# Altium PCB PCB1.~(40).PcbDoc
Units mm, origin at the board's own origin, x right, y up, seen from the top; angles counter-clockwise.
Board outline 145.29 x 144.91 mm, 2 copper layers (Top Layer, Bottom Layer); 41 components, 36 nets, 219 pads, 0 vias.
Unrouted connection lines stored in the file: 9.
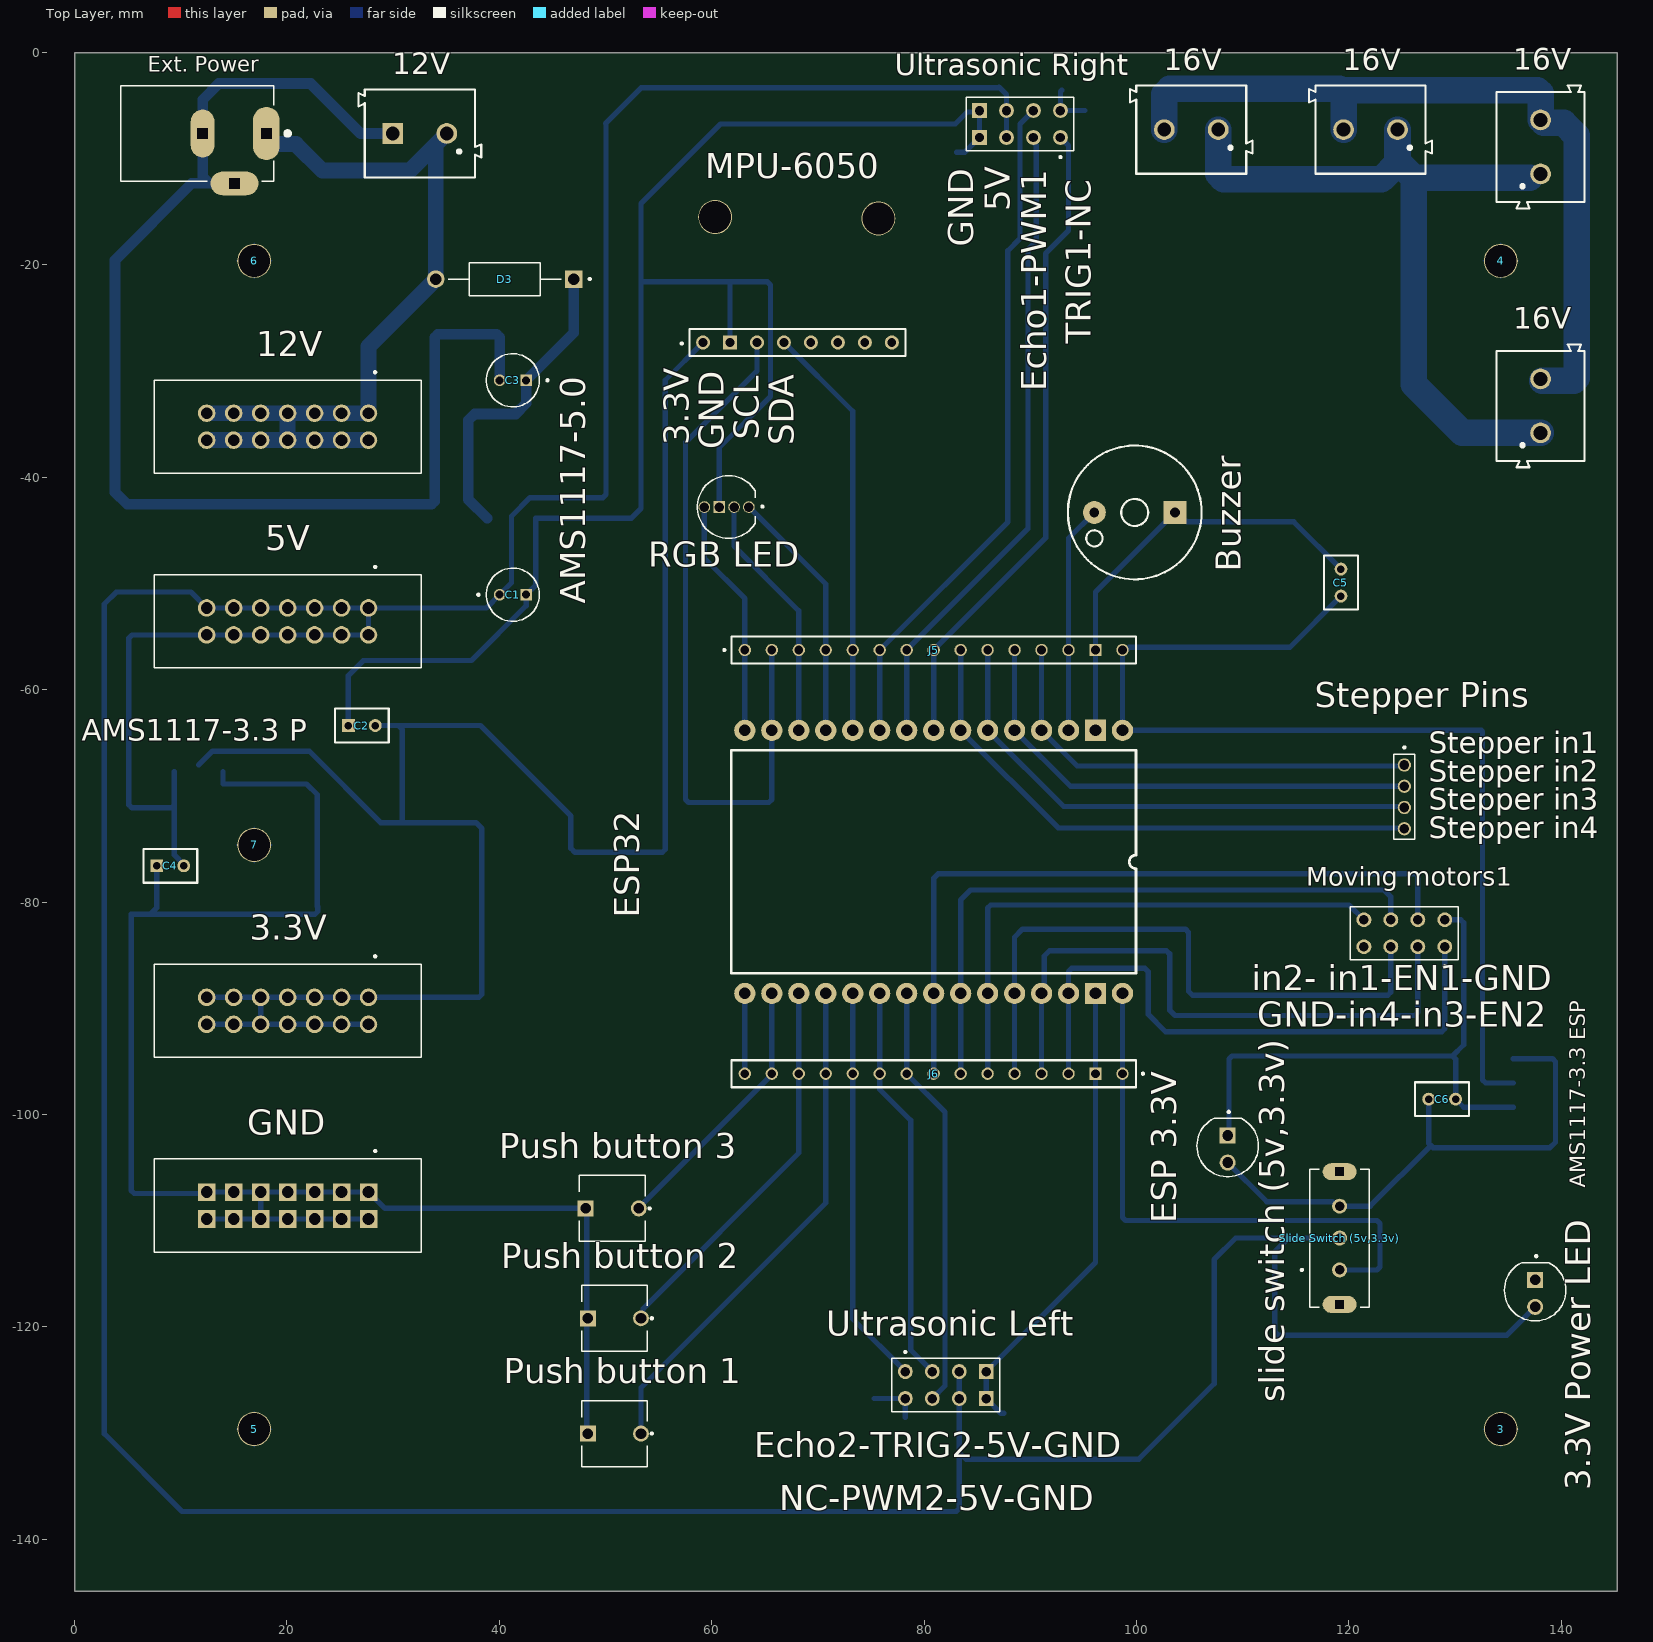
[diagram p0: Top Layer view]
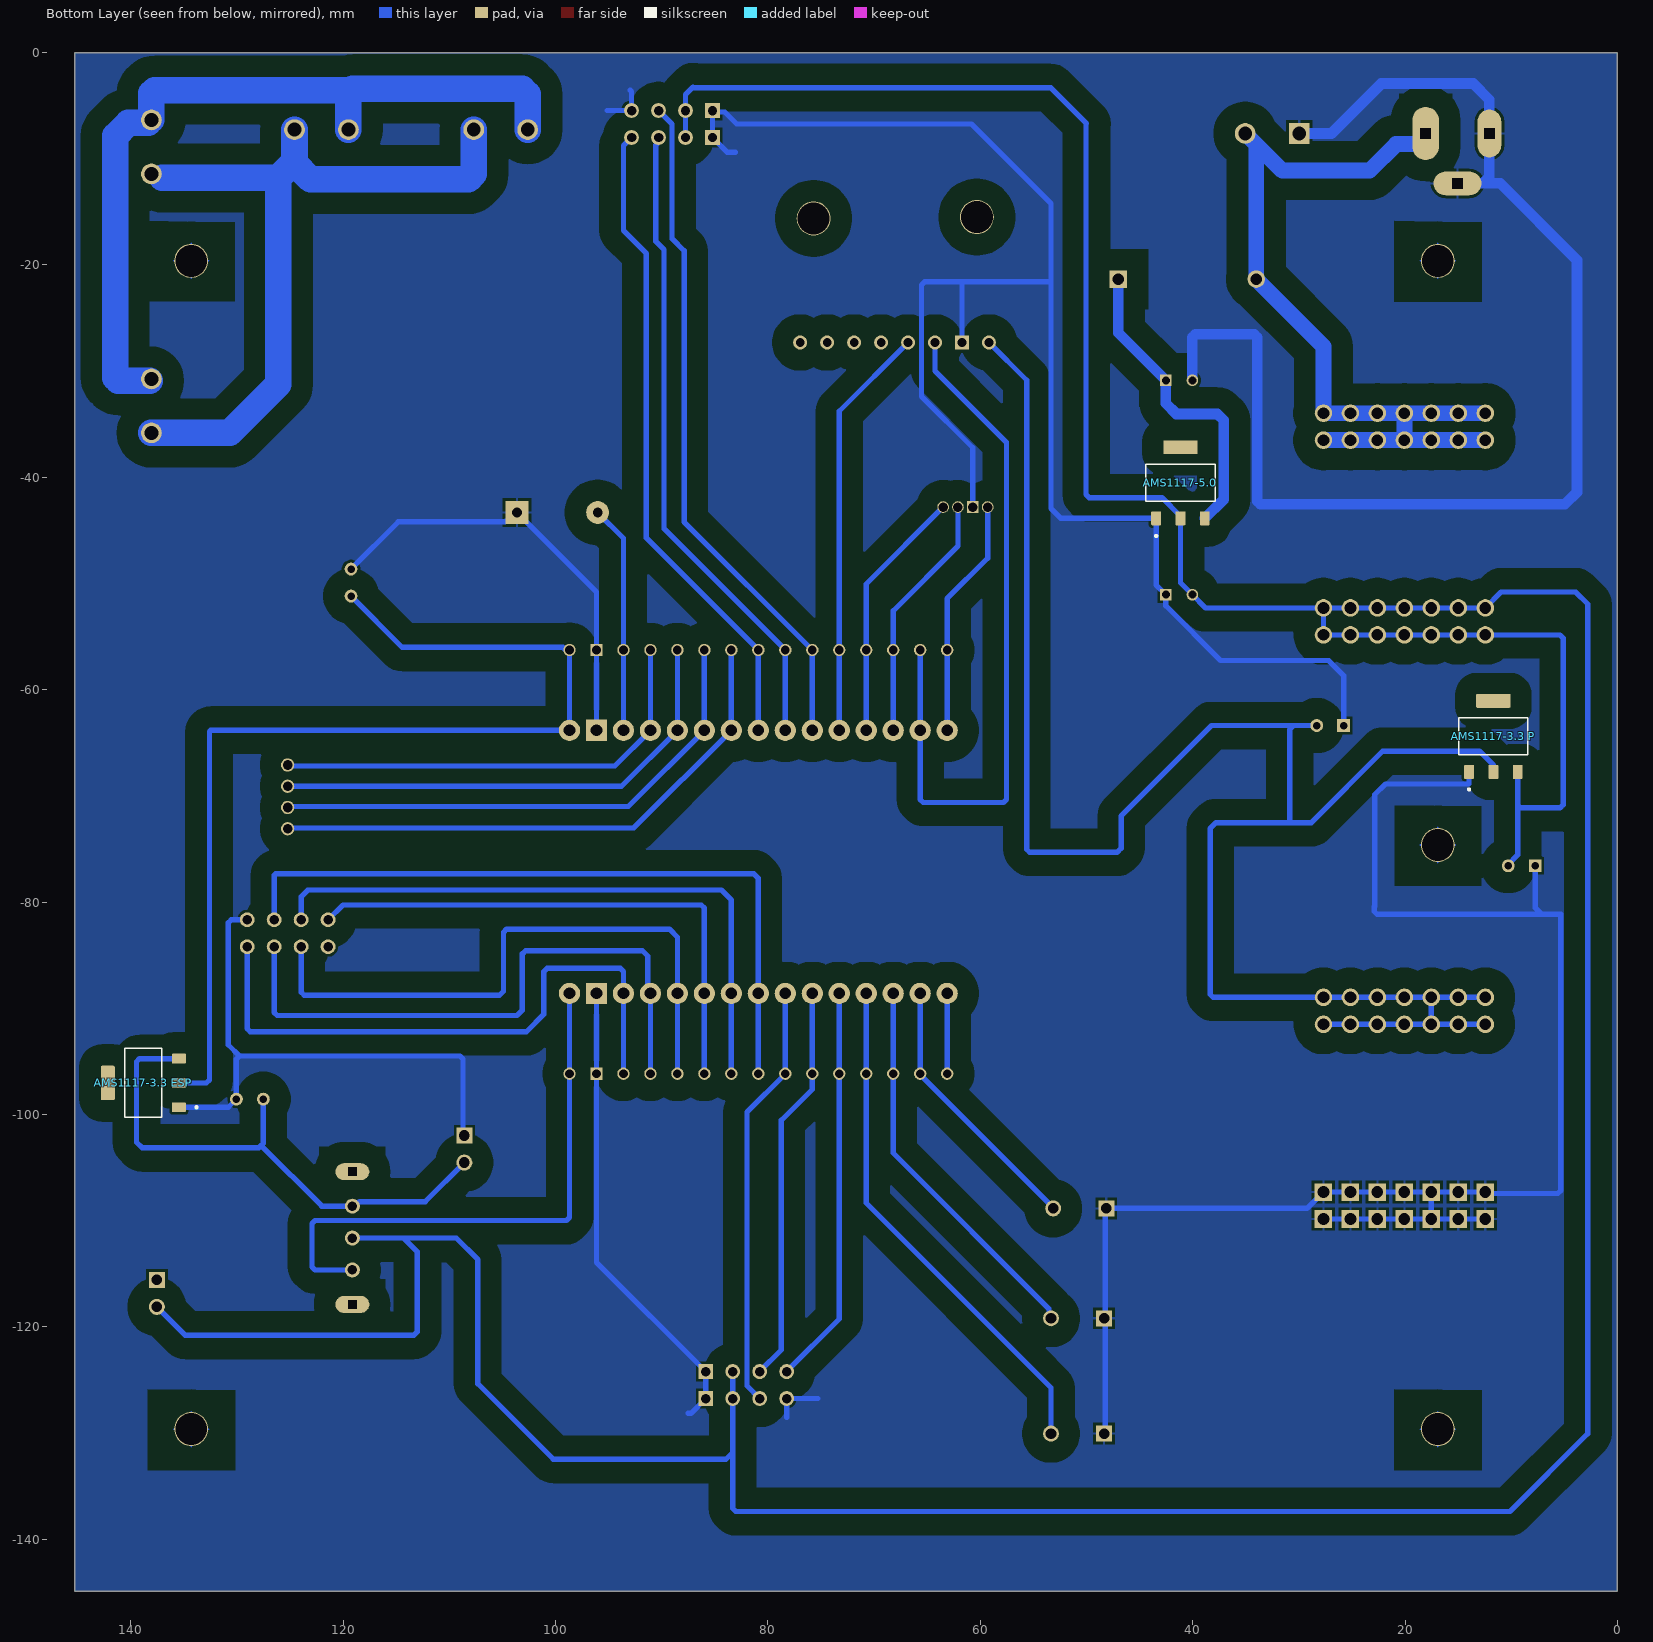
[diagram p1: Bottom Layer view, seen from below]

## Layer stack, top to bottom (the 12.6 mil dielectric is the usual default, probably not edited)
Top Solder: solder mask 0.0102, Solder Resist, Dk 3.5
Top Layer: signal copper 0.0356
Dielectric 1: dielectric 0.32, FR-4, Dk 4.8
Bottom Layer: signal copper 0.0356
Bottom Solder: solder mask 0.0102, Solder Resist, Dk 3.5

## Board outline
0,-144.907 145.288,-144.907 145.288,0 0,0

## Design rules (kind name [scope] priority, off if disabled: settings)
Clearance [All] p1: gap=0.254 ignorepadtopadclearanceinfootprint=FALSE except(0: Arc-Hole Track-Hole SMDPad-Hole THPad-Hole Via-Hole Fill-Hole Poly-Hole Region-Hole Text-Hole; 2: Arc-Poly Track-Poly SMDPad-Poly THPad-Poly)
PolygonConnect [All] p1: connectstyle=Relief reliefconductorwidth=0.254 reliefentries=4 polygonreliefangle="90 Angle" airgapwidth=0.254
RoutingLayers [All] p1: top layer_v5=FALSE bottom layer_v5=TRUE
RoutingVias [All] p1: holewidth=0.711 width=1.27 viastyle="Through Hole" minholewidth=0.711 minwidth=1.27 maxholewidth=0.711 maxwidth=1.27
SolderMaskExpansion [All] p1: expansion=0.102 istentingtop=FALSE
Width [All] p1: maxlimit=2.5 minlimit=0.254 preferedwidth=0.5
29 further rules are at their usual default settings.

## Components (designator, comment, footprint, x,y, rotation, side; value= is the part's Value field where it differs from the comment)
3 "Mounting Hole" PCBComponent_1 134.304,-129.619 r90 top
3.3V "3.3v pin headers block" AMPHENOL_52601-S14-4LF#1 20.066,-90.235 r180 top
"3.3V Power LED" "LED 5mm" "LED 5mm" 137.541,-116.84 r270 top
4 "Mounting Hole" PCBComponent_1 134.304,-19.619 r90 top
5 "Mounting Hole" PCBComponent_1 16.916,-129.619 r90 top
5V "5v pin headers block" AMPHENOL_52601-S14-4LF#1 20.066,-53.568 r180 top
6 "Mounting Hole" PCBComponent_1 16.916,-19.619 r90 top
7 "Mounting Hole" PCBComponent_1 16.916,-74.619 r90 top
12V "12v pin headers block" AMPHENOL_52601-S14-4LF#1 20.066,-35.235 r180 top
12V "From Buck" 691213510002#1 32.512,-7.62 r180 top
16V "From Buck" 691213510002#2 138.049,-8.89 r90 top
16V "From Buck" 691213510002#2 138.049,-33.274 r90 top
16V "From Buck" 691213510002#2 122.036,-7.26 r180 top
16V "From Buck" 691213510002#2 105.156,-7.26 r180 top
"AMS1117-3.3 ESP" "AMS1117-3.3" SOT229P700X180-4N 138.811,-97.028 r0 bottom
"AMS1117-3.3 P" "AMS1117-3.3" SOT229P700X180-4N 11.684,-64.389 r90 bottom
AMS1117-5.0 "AMS1117-5.0" SOT229P700X180-4N 41.148,-40.513 r90 bottom
Buzzer "Buzzer" "Buzzer 5V" 99.832,-43.307 r180 top
C1 "CAP  33UF 50V RADIAL" "CAP  33UF 50V RADIAL"#1 41.275,-51.054 r0 top
C2 "Ceramic Capacitor 100nF" C320C#1 34.051,-56.373 r0 top
C3 "CAP  33UF 50V RADIAL" "CAP  33UF 50V RADIAL"#2 41.275,-30.861 r180 top
C4 "Ceramic Capacitor 100nF" C320C#1 16.017,-69.581 r0 top
C5 "Ceramic Capacitor 100nF" C320C#2 126.253,-56.911 r270 top
C6 "Ceramic Capacitor 100nF" C320C#2 121.778,-105.552 r180 top
D3 "RL207" DIOAD1300W80L670D310 40.513,-21.336 r180 top
ESP32 "ESP32DEVKITV1" ESP32DEVKITV1 81.026,-75.508 r90 top
"ESP 3.3V" "LED 5mm" "LED 5mm" 108.585,-103.251 r270 top (schematic designator "Power ESP 3.3V")
"Ext. Power" "DC Power Jack Female Socket" "DC Power Jack Female Socket" 18.065,-7.62 r180 top
GND "GND pin headers block" AMPHENOL_52601-S14-4LF#2 20.066,-108.568 r180 top
J5 "TS-115-T-A-1" SAMTEC_TS-115-T-A-1#1 80.899,-56.261 r0 top
J6 "TS-115-T-A-1" SAMTEC_TS-115-T-A-1#2 80.899,-96.157 r180 top
"Moving motors1" "Pin header female block 8 pin" "Pin header female block 8 pin"#1 125.222,-82.931 r180 top
MPU-6050 "MPU-6050" MPU-6050 57.658,-28.829 r90 top
"Push button 1" "FSM8JRT" TE_FSM8JRT 53.34,-130.048 r180 top
"Push button 2" "FSM8JRT" TE_FSM8JRT 53.34,-119.189 r180 top
"Push button 3" "FSM8JRT" TE_FSM8JRT 53.137,-108.839 r180 top
"RGB LED" "common cathode" "LED RGB 5mm" 61.595,-42.799 r180 top
"Slide Switch (5v,3.3v)" "slide switch (5v,3.3v)" "Slide switch" 119.126,-111.633 r90 top
"Stepper Pins" "Pin hreader 4 pins" "Pin hreader 4 pins" 125.222,-67.088 r270 top
"Ultrasonic Left" "Pin header female block 8 pin" "Pin header female block 8 pin"#2 82.042,-125.476 r0 top
"Ultrasonic Right" "Pin header female block 8 pin" "Pin header female block 8 pin"#2 89.027,-6.731 r180 top

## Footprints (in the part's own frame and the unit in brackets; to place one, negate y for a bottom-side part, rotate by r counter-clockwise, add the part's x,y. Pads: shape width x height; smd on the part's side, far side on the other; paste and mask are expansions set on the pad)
691213510002#1 [mm]
  round 1.95 hole 1.3: 1(-2.54,0)
  rect 1.95x1.95 hole 1.3: 2(2.54,0)
  silkscreen extent -5.78,-4.15 5.78,4.15, body extent -5.68,-3.94 5.68,4.16, height 10
691213510002#2 [mm]
  round 1.95 hole 1.3: 1(-2.54,0) 2(2.54,0)
  silkscreen extent -5.78,-4.15 5.78,4.15, body extent -5.68,-3.94 5.68,4.16, height 10
AMPHENOL_52601-S14-4LF#1 [mm]
  round 1.65 hole 1.1: 1(-7.62,-1.27) 2(-7.62,1.27) 3(-5.08,-1.27) 4(-5.08,1.27) 5(-2.54,-1.27) 6(-2.54,1.27) 7(0,-1.27) 8(0,1.27) 9(2.54,-1.27) 10(2.54,1.27) 11(5.08,-1.27) 12(5.08,1.27) 13(7.62,-1.27) 14(7.62,1.27)
  silkscreen extent -12.57,-5.23 12.57,4.38, body extent -12.57,-4.38 12.57,4.38, height 9.53
AMPHENOL_52601-S14-4LF#2 [mm]
  rect 1.65x1.65 hole 1.1: 1(-7.62,-1.27) 2(-7.62,1.27) 3(-5.08,-1.27) 4(-5.08,1.27) 5(-2.54,-1.27) 6(-2.54,1.27) 7(0,-1.27) 8(0,1.27) 9(2.54,-1.27) 10(2.54,1.27) 11(5.08,-1.27) 12(5.08,1.27) 13(7.62,-1.27) 14(7.62,1.27)
  silkscreen extent -12.57,-5.23 12.57,4.38, body extent -12.57,-4.38 12.57,4.38, height 9.53
"Buzzer 5V" [mil]
  rect 85x85 hole 36: NEG(-149.61,0)
  round 85 hole 36: POS(149.61,0)
  silkscreen extent -248,-248 248,248, body extent -236,-236 236,236, height 394
C320C#1 [mm]
  rect 1.21x1.21 hole 0.71: 1(-8.27,-7)
  round 1.21 hole 0.71: 2(-5.73,-7)
  silkscreen extent -9.54,-8.59 -4.46,-5.41, body extent -9.53,-8.57 -4.45,-5.4, height 7.1
C320C#2 [mm]
  round 1.21 hole 0.71: 1(-8.27,-7) 2(-5.73,-7)
  silkscreen extent -9.54,-8.59 -4.46,-5.41, body extent -9.52,-8.57 -4.45,-5.4, height 7.1
"CAP  33UF 50V RADIAL"#1 [mm]
  rect 1.1x1.1 hole 0.75: N(1.25,0)
  round 1.1 hole 0.75: P(-1.25,0)
  silkscreen extent -3.35,-2.5 2.5,2.5, body extent -2.49,-2.5 2.5,2.5, height 11
"CAP  33UF 50V RADIAL"#2 [mm]
  round 1.1 hole 0.75: N(1.25,0)
  rect 1.1x1.1 hole 0.75: P(-1.25,0)
  silkscreen extent -3.35,-2.5 2.5,2.5, body extent -2.49,-2.5 2.5,2.5, height 11
"DC Power Jack Female Socket" [mm]
  oval 2.5x5 hole 1 square: 1(0,0)
  oval 2.25x4.5 hole 1 square: 2(6,0)
  oval 4.5x2.25 hole 1 square: 3(3,4.7)
  silkscreen extent -2.2,-4.5 13.7,4.5, body extent -0.7,-4.5 13.7,4.9, height 11
DIOAD1300W80L670D310 [mm]
  round 1.65 hole 1.1: A(6.5,0)
  rect 1.65x1.65 hole 1.1: C(-6.5,0)
  silkscreen extent -8.1,-1.55 5.32,1.55, body extent -6.9,-1.95 6.9,1.65, height 3.6
ESP32DEVKITV1 [mm]
  round 2 hole 1.1: 1(11.684,-17.653) 3(11.684,-12.573) 4(11.684,-10.033) 5(11.684,-7.493) 6(11.684,-4.953) 7(11.684,-2.413) 8(11.684,0.127) 9(11.684,2.667) 10(11.684,5.207) 11(11.684,7.747) 12(11.684,10.287) 13(11.684,12.827) 14(11.684,15.367) 15(11.684,17.907) 16(-13.086,17.907) 17(-13.086,15.367) 18(-13.086,12.827) 19(-13.086,10.287) 20(-13.086,7.747) 21(-13.086,5.207) 22(-13.086,2.667) 23(-13.086,0.127) 24(-13.086,-2.413) 25(-13.086,-4.953) 26(-13.086,-7.493) 27(-13.086,-10.033) 28(-13.086,-12.573) 30(-13.086,-17.653)
  rect 2x2 hole 1.1: 2(11.684,-15.113) 29(-13.086,-15.113)
  silkscreen extent -11.2,-18.92 9.79,19.18, body extent -15.13,-28.49 13.86,24.48, height 8.36
"LED 5mm" [mm]
  round 1.508 hole 1: A(1.27,0)
  rect 1.508x1.508 hole 1: C(-1.27,0)
  silkscreen extent -3.6,-2.9 2.6,2.9, body extent -2.88,-2.9 2.51,2.9, height 12.1
"LED RGB 5mm" [mm]
  round 1.1 hole 0.9: 1(-1.905,0) 2(-0.508,0) 4(2.286,0)
  rect 1.1x1.1 hole 0.9: 3(0.889,0)
  silkscreen extent -3.27,-2.95 2.95,2.95, body extent -2.47,-3.05 2.98,2.84, height 9.6
MPU-6050 [mil]
  round 52 hole 32: 01(60,-60) 03(60,-260) 04(60,-360) 05(60,-460) 06(60,-560) 07(60,-660) 08(60,-760)
  rect 52x52 hole 32: 02(60,-160)
  round 125.98 hole 118.11: ""(520,-710) ""(525,-105)
  silkscreen extent 10,-810 110,23, body extent 15,-811 615,-9, height 612
PCBComponent_1 [mm]
  round 3.2 hole 3: ""(0,0)
  Bottom Layer lines w0.15: 0,1.649 0,-1.651 ; -1.651,0 1.649,0
"Pin header female block 8 pin"#1 [mm]
  round 1.398 hole 0.89: 1(-3.81,1.27) 2(-1.27,1.27) 3(1.27,1.27) 4(3.81,1.27) 5(-3.81,-1.27) 6(-1.27,-1.27) 7(1.27,-1.27) 8(3.81,-1.27)
  silkscreen extent -5.08,-2.52 5.08,3.21, body extent -5.08,-2.51 5.08,2.51, height 6.22
"Pin header female block 8 pin"#2 [mm]
  round 1.398 hole 0.89: 1(-3.81,1.27) 2(-1.27,1.27) 3(1.27,1.27) 5(-3.81,-1.27) 6(-1.27,-1.27) 7(1.27,-1.27)
  rect 1.398x1.398 hole 0.89: 4(3.81,1.27) 8(3.81,-1.27)
  silkscreen extent -5.08,-2.52 5.08,3.21, body extent -5.08,-2.51 5.08,2.51, height 6.22
"Pin hreader 4 pins" [mm]
  round 1.25 hole 0.9: 1(0,0) 2(2,0) 3(4,0) 4(6,0)
  silkscreen extent -1.75,-1 7,1, body extent -1.01,-1.02 6.98,0.98, height 5.78
SAMTEC_TS-115-T-A-1#1 [mil]
  round 45.78 hole 32: 01(-700,0) 02(-600,0) 03(-500,0) 04(-400,0) 05(-300,0) 06(-200,0) 07(-100,0) 08(0,0) 09(100,0) 10(200,0) 11(300,0) 12(400,0) 13(500,0) 15(700,0)
  rect 45.78x45.78 hole 32: 14(600,0)
  silkscreen extent -780,-50 750,50, body extent -754,-50 754,50, height 326
SAMTEC_TS-115-T-A-1#2 [mil]
  round 45.78 hole 32: 01(-700,0) 03(-500,0) 04(-400,0) 05(-300,0) 06(-200,0) 07(-100,0) 08(0,0) 09(100,0) 10(200,0) 11(300,0) 12(400,0) 13(500,0) 14(600,0) 15(700,0)
  rect 45.78x45.78 hole 32: 02(-600,0)
  silkscreen extent -780,-50 750,50, body extent -754,-50 754,50, height 326
"Slide switch" [mm]
  round 1.408 hole 0.9: 1(-3,0) 2(0,0) 3(3,0)
  oval 1.6x3.2 hole 0.8 square: SH1(-6.25,0) SH2(6.25,0)
  silkscreen extent -6.5,-2.8 6.5,3.66, body extent -6.5,-5.8 6.5,2.8, height 6
SOT229P700X180-4N [mm]
  rrect15% 1.31x0.93 smd: 1(-3.345,2.29) 2(-3.345,0) 3(-3.345,-2.29)
  rrect15% 1.31x3.24 smd: 4(3.345,0)
  silkscreen extent -5.1,-3.25 1.75,3.25, body extent -3.5,-3.25 3.5,3.25, height 1.8
TE_FSM8JRT [mil]
  round 59 hole 39: 1(0,0)
  rect 59x59 hole 39: 2(197,0)
  silkscreen extent -44,-122 221,122, body extent -22,-122 222,122, height 372

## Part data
3.3V 5V 12V GND: library part 52601-S14-4LF, Package=None
"3.3V Power LED" "ESP 3.3V": "Red 623nm LED Indication - Discrete 1.9V Radial", Package=None
12V 16V 16V 16V 16V: library part "Terminal Block", "2 Position Wire to Board Terminal Block Horizontal with Board 0.200 (5.08mm) Through Hole", Package=None
"AMS1117-3.3 ESP" "AMS1117-3.3 P" AMS1117-5.0 J5 J6 "Moving motors1" "Stepper Pins" "Ultrasonic Left" "Ultrasonic Right": Package=None
Buzzer: library part "Buzzer 5V", "BUZZER 2.3KHZ 4-6VDC", Package=None
C1 C3: "NHG-A", Package=None
C2 C4 C5 C6: "0.1ÂµF Â±20% 50V Ceramic Capacitor Z5U Radial", Package="Radial KEMET"
D3: "Semiconductors and Actives, Power Diodes, Discretes (diodes, transistors, thyristors ...), Diodes", Package=None
"Ext. Power": "2.0 mm Center Pin, 2.5 A, Right Angle, Through Hole, Dc Power Jack Connector", Package=None
"Push button 1" "Push button 2" "Push button 3": "Tactile Switches PUSHBUTTON SWITCH TACT", Package=None
"RGB LED": library part "LED RGB 5mm", Package=None
"Slide Switch (5v,3.3v)": library part "Slide switch", Package=None

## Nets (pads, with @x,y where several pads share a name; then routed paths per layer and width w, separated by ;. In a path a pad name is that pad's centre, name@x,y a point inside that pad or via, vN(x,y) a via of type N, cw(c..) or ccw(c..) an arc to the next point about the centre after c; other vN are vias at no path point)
3.3V: 3.3V.1 3.3V.2 3.3V.3 3.3V.4 3.3V.5 3.3V.6 3.3V.7 3.3V.8 3.3V.9 3.3V.10 3.3V.11 3.3V.12 3.3V.13 3.3V.14 "AMS1117-3.3 P.2" C2.2 MPU-6050.01 | length 182.3
  Bottom Layer w0.5: 11.684,-67.095 12.993,-65.786 22.098,-65.786 28.829,-72.517 30.861,-72.517 ; 3.3V.14 3.3V.12 3.3V.10 ; 3.3V.13 3.3V.11 3.3V.9 ; 3.3V.2 3.3V.4 3.3V.6 3.3V.8 3.3V.10 ; C2.2 30.48,-63.373 ; MPU-6050.01 55.626,-30.861 55.626,-75.018 55.333,-75.311 47.117,-75.311 46.736,-74.93 46.736,-71.882 38.227,-63.373 30.48,-63.373 ; 3.3V.10 3.3V.9 ; 3.3V.9 3.3V.7 3.3V.5 3.3V.3 3.3V.1 38.061,-88.965 38.354,-88.672 38.354,-73.064 37.807,-72.517 30.861,-72.517 ; 30.48,-63.373 30.861,-63.754 30.861,-72.517
+5: 5V.1 5V.2 5V.3 5V.4 5V.5 5V.6 5V.7 5V.8 5V.9 5V.10 5V.11 5V.12 5V.13 5V.14 "3.3V Power LED.A" "AMS1117-3.3 P.3" "Slide Switch (5v,3.3v).2" "Ultrasonic Left.3" "Ultrasonic Left.7" "Ultrasonic Right.3" "Ultrasonic Right.7" AMS1117-5.0.2 C1.P C4.2 | length 450.9
  Bottom Layer w0.5: 9.394,-67.734 9.394,-70.827 ; C4.2 10.287,-76.451 9.394,-75.558 9.394,-70.827 ; 83.312,-124.206 83.312,-126.746 83.312,-131.826 ; 87.757,-8.001 87.757,-5.461 87.757,-3.954 87.05,-3.247 86.995,-3.302 53.373,-3.302 49.991,-6.684 50.038,-6.731 50.038,-41.617 49.745,-41.91 42.906,-41.91 41.148,-43.668 AMS1117-5.0.2 41.148,-49.931 C1.P 38.781,-52.298 5V.1 ; 119.126,-111.633 114.3,-111.633 ; 137.541,-118.11 134.874,-120.777 113.323,-120.777 113.03,-120.484 113.03,-112.903 114.3,-111.633 ; 9.394,-70.827 9.101,-71.12 5.412,-71.12 5.119,-70.827 5.119,-55.131 5.412,-54.838 5V.14 5V.12 5V.10 5V.8 5V.6 5V.4 5V.2 5V.1 ; 5V.1 5V.3 5V.5 5V.7 5V.9 5V.11 5V.13 10.948,-50.8 3.937,-50.8 2.794,-51.943 2.794,-130.048 10.125,-137.379 83.019,-137.379 83.312,-137.086 83.312,-131.826 ; 83.312,-131.826 83.947,-132.461 100.203,-132.461 107.315,-125.349 107.315,-113.665 109.347,-111.633 114.3,-111.633
+12: 12V.1 12V.2@27.686,-36.505 12V.3 12V.4 12V.5 12V.6 12V.7 12V.8 12V.9 12V.10 12V.11 12V.12 12V.13 12V.14 "Ext. Power.1" D3.A | length 82.3
  Bottom Layer w0.5: 18.065,-7.62 18.065,-7.696 18.989,-8.62 ; 34.013,-9.021 35.052,-7.981 12V.1@35.052,-7.62
  Bottom Layer w1.5: 12V.14 12V.12 12V.10 12V.8 ; 12V.13 12V.11 12V.9 12V.7 ; 18.989,-8.62 20.845,-8.62 23.345,-11.12 31.552,-11.12 12V.1@35.052,-7.62 ; 12V.2@27.686,-36.505 12V.4 12V.6 12V.8 ; D3.A 27.686,-27.663 27.686,-33.965 12V.3 12V.5 12V.7 ; D3.A@34.013,-21.313 34.013,-9.021 ; 12V.8 12V.7
GND: 12V.2@29.972,-7.62 "3.3V Power LED.C" "AMS1117-3.3 ESP.1" "AMS1117-3.3 P.1" "ESP 3.3V.C" "Ext. Power.2" "Ext. Power.3" "Moving motors1.4" "Moving motors1.5" "Push button 1.2" "Push button 2.2" "Push button 3.2" "RGB LED.3" "Ultrasonic Left.4" "Ultrasonic Left.5" "Ultrasonic Left.8" "Ultrasonic Right.4" "Ultrasonic Right.5" "Ultrasonic Right.8" AMS1117-5.0.1 Buzzer.NEG C1.N C2.1 C3.N C4.1 C5.1 C6.1 ESP32.2 ESP32.29 GND.1 GND.2 GND.3 GND.4 GND.5 GND.6 GND.7 GND.8 GND.9 GND.10 GND.11 GND.12 GND.13 GND.14 J5.14 J6.02 MPU-6050.02 | length 575.7
  Bottom Layer w0.5: C4.1 7.747,-80.518 7.112,-81.153 ; GND.14 GND.12 GND.10 ; 13.974,-67.734 13.974,-68.877 21.848,-68.877 22.86,-69.889 22.86,-80.391 22.915,-80.446 22.915,-80.86 22.622,-81.153 7.112,-81.153 ; C2.1 25.781,-58.674 27.201,-57.254 37.361,-57.254 42.525,-52.09 C1.N 43.438,-50.141 AMS1117-5.0.1 52.408,-43.858 53.34,-42.926 53.34,-21.463 ; GND.2 GND.4 GND.6 GND.8 GND.10 ; 33.616,-42.545 33.909,-42.252 ; 33.909,-26.836 34.202,-26.543 ; 39.732,-26.543 40.025,-26.836 ; 48.336,-130.048 48.235,-129.946 48.235,-108.941 48.133,-108.839 29.227,-108.839 GND.1 GND.3 GND.5 GND.7 GND.9 ; 60.706,-42.799 60.706,-37.211 65.532,-32.385 65.532,-21.883 65.239,-21.59 61.722,-21.59 ; MPU-6050.02 61.722,-21.59 ; 75.311,-126.746 78.232,-126.746 78.232,-128.524 ; 83.058,-9.398 83.82,-9.398 85.217,-8.001 85.217,-5.461 85.077,-5.601 84.061,-5.601 82.931,-6.731 60.833,-6.731 53.34,-14.224 53.34,-21.463 ; 87.503,-128.143 87.249,-128.143 85.852,-126.746 85.852,-124.206 96.139,-113.919 J6.02 ESP32.29 ; 92.964,-3.556 92.837,-3.683 92.837,-5.461 95.123,-5.461 ; ESP32.2 J5.14 96.139,-50.8 Buzzer.NEG 104.462,-44.137 104.695,-44.137 104.754,-44.196 114.808,-44.196 C5.1 ; 108.585,-101.981 108.712,-101.854 108.712,-94.781 109.005,-94.488 129.755,-94.488 ; 129.032,-81.661 130.517,-81.661 130.81,-81.954 130.81,-93.433 129.755,-94.488 ; 135.466,-99.318 130.814,-99.318 C6.1 130.048,-94.781 129.755,-94.488 ; 7.112,-81.153 5.334,-81.153 5.334,-107.149 5.627,-107.442 12.302,-107.442 GND.13 GND.11 GND.9 ; GND.10 GND.9 ; 53.34,-21.463 53.467,-21.59 61.722,-21.59
  Bottom Layer w1: 15.065,-12.32 12.701,-12.32 ; 12V.2@29.972,-7.62 26.924,-7.62 22.225,-2.921 13.589,-2.921 12.065,-4.445 12.065,-11.684 12.701,-12.32 ; 33.616,-42.545 4.953,-42.545 3.81,-41.402 3.81,-19.558 11.048,-12.32 12.701,-12.32 ; 33.909,-42.252 33.909,-26.836 ; 34.202,-26.543 39.732,-26.543 ; C3.N 40.025,-26.836
Net16V_1: 16V.1 | length 72.4
  Bottom Layer w0.5: 137.031,-11.811 137.135,-11.707 137.772,-11.707 16V.1@138.049,-11.43
  Bottom Layer w2.5: 16V.1@107.696,-7.26 107.696,-11.43 108.204,-11.938 123.053,-11.938 124.576,-10.415 ; 16V.1@124.576,-7.26 124.576,-10.276 126.111,-11.811 ; 137.031,-11.811 126.111,-11.811 ; 16V.1@138.049,-35.814 130.683,-35.814 126.111,-31.242 126.111,-11.811
Net16V_2: 16V.2 | length 75.7
  Bottom Layer w0.5: 102.616,-3.937 103.124,-3.429 ; 119.077,-3.429 119.496,-3.849 119.789,-3.556 ; 137.756,-3.556 138.049,-3.849 ; 16V.2@138.049,-30.734 16V.2@138.21,-30.895 ; 16V.2@138.049,-6.35 16V.2@138.326,-6.627 ; 141.151,-30.895 141.444,-30.602
  Bottom Layer w2.5: 16V.2@102.616,-7.26 102.616,-3.937 ; 103.124,-3.429 119.077,-3.429 ; 16V.2@119.496,-7.26 119.496,-3.849 ; 119.789,-3.556 137.756,-3.556 ; 16V.2@138.049,-6.35 138.049,-3.849 ; 16V.2@138.21,-30.895 141.151,-30.895 ; 16V.2@138.326,-6.627 140.231,-6.627 141.444,-7.84 141.444,-30.602
"NetAMS1117-3.3 ESP_2": "AMS1117-3.3 ESP.2" C5.2 ESP32.1 J5.15 | length 100
  Bottom Layer w0.5: C5.2 114.427,-56.007 99.303,-56.007 99.176,-56.134 98.806,-56.134 J5.15 ESP32.1 132.461,-63.824 132.588,-63.951 132.588,-96.735 132.881,-97.028 135.466,-97.028
"NetAMS1117-3.3 ESP_3": "AMS1117-3.3 ESP.3" "ESP 3.3V.A" "Slide Switch (5v,3.3v).3" C6.2 | length 51.4
  Bottom Layer w0.5: 108.585,-104.521 112.268,-108.204 118.451,-108.204 118.88,-108.633 119.126,-108.633 121.999,-108.633 127.718,-102.914 ; C6.2 127.508,-102.704 127.718,-102.914 ; 135.466,-94.738 139.153,-94.738 139.446,-95.031 139.446,-102.616 138.938,-103.124 127.928,-103.124 127.718,-102.914
NetAMS1117-5.0_3: AMS1117-5.0.3 C3.P D3.C | length 29.6
  Bottom Layer w1: AMS1117-5.0.3 37.084,-42.084 37.084,-34.622 37.67,-34.036 41.529,-34.036 42.525,-33.04 C3.P 47.013,-26.373 D3.C
NetBuzzer_POS: Buzzer.POS ESP32.3 J5.13 | length 21.5
  Bottom Layer w0.5: ESP32.3 J5.13 93.599,-45.74 Buzzer.POS
NetESP32_4: "Stepper Pins.1" ESP32.4 J5.12 | length 42.6
  Bottom Layer w0.5: J5.12 ESP32.4 94.418,-67.183 124.714,-67.183
NetESP32_5: "Stepper Pins.2" ESP32.5 J5.11 | length 46.1
  Bottom Layer w0.5: J5.11 ESP32.5 93.783,-69.088 124.841,-69.088
NetESP32_6: "Stepper Pins.3" ESP32.6 J5.10 | length 49.3
  Bottom Layer w0.5: J5.10 ESP32.6 93.148,-70.993 124.714,-70.993
NetESP32_7: "Stepper Pins.4" ESP32.7 J5.09 | length 52.5
  Bottom Layer w0.5: J5.09 ESP32.7 92.64,-73.025 124.587,-73.025
NetESP32_8: "Ultrasonic Right.1" ESP32.8 J5.08 | length 61.4
  Bottom Layer w0.5: ESP32.8 J5.08 91.44,-45.72 91.44,-18.923 93.599,-16.764 93.599,-8.763 92.837,-8.001
NetESP32_9: "Ultrasonic Right.2" ESP32.9 J5.07 | length 61
  Bottom Layer w0.5: ESP32.9 J5.07 89.789,-44.831 89.789,-18.542 90.551,-17.78 90.551,-8.743 90.469,-8.661 90.469,-8.173 90.297,-8.001
NetESP32_10: "Ultrasonic Right.6" ESP32.10 J5.06 | length 64.4
  Bottom Layer w0.5: ESP32.10 J5.06 87.884,-44.196 87.884,-18.669 89.027,-17.526 89.027,-6.731 90.297,-5.461
NetESP32_11: ESP32.11 J5.05 MPU-6050.04 | length 39.2
  Bottom Layer w0.5: MPU-6050.04 73.279,-33.782 ESP32.11
NetESP32_12: "RGB LED.1" ESP32.12 J5.04 | length 24
  Bottom Layer w0.5: 63.5,-42.799 70.739,-50.038 J5.04 ESP32.12
NetESP32_13: "RGB LED.2" ESP32.13 J5.03 | length 23.6
  Bottom Layer w0.5: 62.103,-42.799 62.103,-46.474 68.199,-52.57 J5.03 ESP32.13
NetESP32_14: ESP32.14 J5.02 MPU-6050.03 | length 68.2
  Bottom Layer w0.5: MPU-6050.03 64.262,-29.972 57.531,-36.703 57.531,-70.319 57.824,-70.612 65.366,-70.612 65.659,-70.319 ESP32.14 J5.02
NetESP32_15: "RGB LED.4" ESP32.15 J5.01 | length 22.6
  Bottom Layer w0.5: 59.309,-42.799 59.309,-47.617 63.119,-51.427 J5.01 ESP32.15
NetESP32_16: ESP32.16 J6.15 | length 7.6
  Bottom Layer w0.5: J6.15 ESP32.16
NetESP32_17: "Push button 3.1" ESP32.17 J6.14 | length 25.4
  Bottom Layer w0.5: 53.137,-108.839 53.137,-108.759 65.659,-96.237 J6.14 ESP32.17
NetESP32_18: "Push button 2.1" ESP32.18 J6.13 | length 36.8
  Bottom Layer w0.5: 53.34,-119.189 53.531,-118.998 53.531,-118.3 68.199,-103.632 J6.13 ESP32.18
NetESP32_19: "Push button 1.1" ESP32.19 J6.12 | length 48.7
  Bottom Layer w0.5: 53.34,-130.048 53.34,-125.73 70.739,-108.331 J6.12 ESP32.19
NetESP32_20: "Ultrasonic Left.1" ESP32.20 J6.11 | length 37.7
  Bottom Layer w0.5: ESP32.20 73.279,-119.253 78.232,-124.206
NetESP32_21: "Ultrasonic Left.2" ESP32.21 J6.10 | length 37.7
  Bottom Layer w0.5: ESP32.21 J6.10 75.819,-97.631 78.74,-100.552 78.74,-122.174 80.772,-124.206
NetESP32_22: "Ultrasonic Left.6" ESP32.22 J6.09 | length 40.1
  Bottom Layer w0.5: ESP32.22 J6.09 81.975,-99.773 81.975,-125.543 80.772,-126.746
NetESP32_23: "Moving motors1.6" ESP32.23 J6.08 | length 68.4
  Bottom Layer w0.5: J6.08 ESP32.23 80.899,-77.763 81.319,-77.343 126.365,-77.343 126.492,-77.47 126.492,-81.661
NetESP32_24: "Moving motors1.7" ESP32.24 J6.07 | length 59.7
  Bottom Layer w0.5: J6.07 ESP32.24 83.439,-79.795 84.367,-78.867 123.317,-78.867 123.952,-79.502 123.952,-81.661
NetESP32_25: "Moving motors1.8" ESP32.25 J6.06 | length 51.7
  Bottom Layer w0.5: J6.06 ESP32.25 85.979,-80.557 86.272,-80.264 120.015,-80.264 121.412,-81.661
NetESP32_26: "Moving motors1.3" ESP32.26 J6.05 | length 59.1
  Bottom Layer w0.5: J6.05 ESP32.26 88.519,-83.312 89.281,-82.55 104.609,-82.55 104.902,-82.843 104.902,-88.392 105.283,-88.773 123.659,-88.773 123.952,-88.48 123.952,-83.934
NetESP32_27: "Moving motors1.2" ESP32.27 J6.04 | length 58.7
  Bottom Layer w0.5: J6.04 ESP32.27 91.313,-88.34 91.313,-85.09 91.821,-84.582 102.831,-84.582 103.124,-84.875 103.124,-90.17 103.632,-90.678 126.199,-90.678 126.492,-90.385 126.492,-83.988
NetESP32_28: "Moving motors1.1" ESP32.28 J6.03 | length 57.5
  Bottom Layer w0.5: J6.03 93.599,-86.526 93.892,-86.233 100.799,-86.233 101.092,-86.526 101.092,-90.551 102.743,-92.202 128.739,-92.202 129.032,-91.909 129.032,-84.58
NetESP32_30: "Slide Switch (5v,3.3v).1" ESP32.30 J6.01 | length 53.6
  Bottom Layer w0.5: ESP32.30 J6.01 98.679,-109.689 98.972,-109.982 122.643,-109.982 122.936,-110.275 122.936,-114.34 122.643,-114.633 119.126,-114.633
pads on no net: 3. 4. 5. 6. 7. "AMS1117-3.3 ESP.4" "AMS1117-3.3 P.4" "Slide Switch (5v,3.3v).SH1" "Slide Switch (5v,3.3v).SH2" AMS1117-5.0.4 MPU-6050. MPU-6050.05 MPU-6050.06 MPU-6050.07 MPU-6050.08

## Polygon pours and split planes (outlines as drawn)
GND on Bottom Layer "GND_L02_P000" (solid, pour order 0): 0,-144.907 145.288,-144.907 145.288,0 0,0

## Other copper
Bottom Layer:
  pour cut-out: 130.152,-125.984 138.407,-125.857 138.407,-133.486 130.152,-133.486
  pour cut-out: 130.152,-15.984 138.407,-15.857 138.407,-23.486 130.152,-23.486
  pour cut-out: 12.763,-15.984 21.018,-15.857 21.018,-23.486 12.763,-23.486
  pour cut-out: 12.763,-125.984 21.018,-125.857 21.018,-133.486 12.763,-133.486
  pour cut-out: 12.763,-70.984 21.018,-70.857 21.018,-78.486 12.763,-78.486

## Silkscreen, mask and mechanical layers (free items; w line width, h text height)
Top Overlay:
  text "5V" at 88.851,-14.93 h4 r90
  text "GND" at 85.428,-18.299 h4 r90
  text "TRIG1-NC" at 96.471,-27.403 h4 r90
  text "Echo1-PWM1" at 92.286,-31.877 h4 r90
  text "SCL" at 65.235,-36.446 h4 r90
  text "3.3V" at 58.631,-36.957 h4 r90
  text "SDA" at 68.537,-36.973 h4 r90
  text "GND" at 61.933,-37.343 h4 r90
  text "Stepper in1" at 127.508,-66.688 h3.5
  text "Stepper in2" at 127.508,-69.355 h3.5
  text "Stepper in3" at 127.508,-72.022 h3.5
  text "Stepper in4" at 127.508,-74.689 h3.5
  text "in2- in1-EN1-GND" at 110.871,-89.111 h4
  text "GND-in4-in3-EN2" at 111.379,-92.54 h4
  text "Echo2-TRIG2-5V-GND" at 63.991,-133.053 h4
  text "NC-PWM2-5V-GND" at 66.376,-138.049 h4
